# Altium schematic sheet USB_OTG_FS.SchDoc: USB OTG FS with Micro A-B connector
size A4; Date: 25-FEB-2015; Author: A.B; CompanyName: STMicroelectronics; Address1: 12, Rue Jules HOROWITZ; Address2: 38019 Grenoble; Address3: FRANCE; DocumentNumber: MB1191; Revision: B-02; SheetNumber: 8; SheetTotal: 13; Project: STM32F746G-DISCO
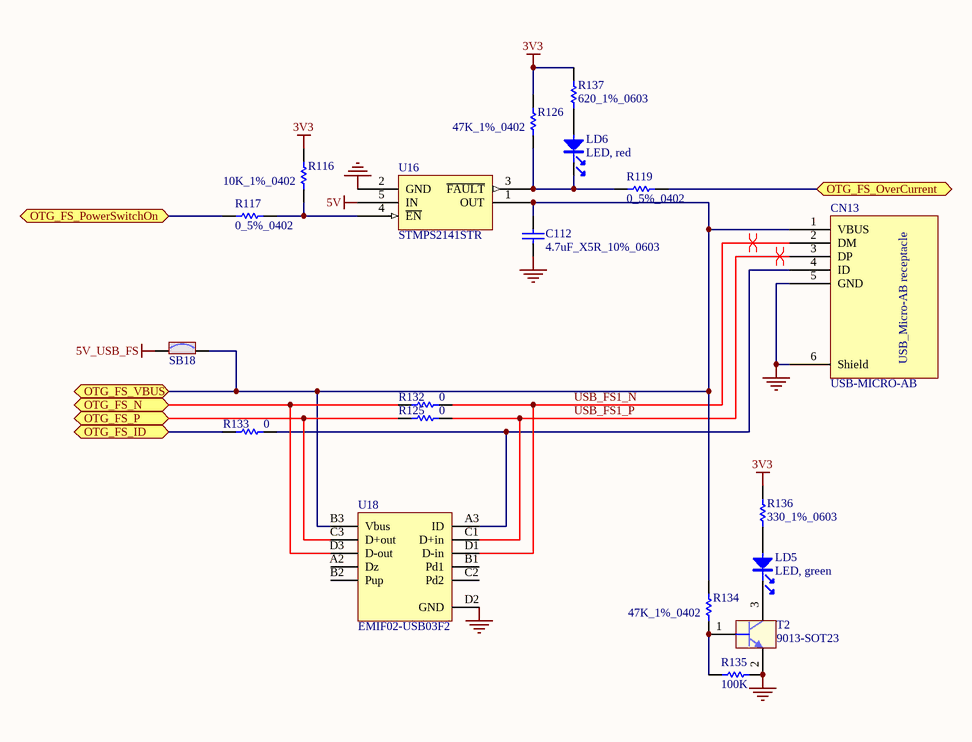
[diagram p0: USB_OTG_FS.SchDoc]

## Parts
C112  4.7uF_X5R_10%_0603  [0603C]
CN13  USB-MICRO-AB  [USB-MICRO-AB]
LD5  LED, green  [0603D]
LD6  LED, red  [0603D]
R116  10K_1%_0402  [0402R]
R117  0_5%_0402  [0402R]
R119  0_5%_0402  [0402R]
R125  0  [0402R]
R126  47K_1%_0402  [0402R]
R132  0  [0402R]
R133  0  [0402R]
R134  47K_1%_0402  [0402R]
R135  100K  [0402R]
R136  330_1%_0603  [0603R]
R137  620_1%_0603  [0603R]
SB18  Solder Bridge ON  [JP2_SMD]  (value not drawn)
T2  9013-SOT23  [SOT23]
U16  STMPS2141STR  [SOT23-5L]
U18  EMIF02-USB03F2  [Flip Chip]

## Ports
OTG_FS_ID, OTG_FS_N, OTG_FS_OverCurrent, OTG_FS_P, OTG_FS_PowerSwitchOn, OTG_FS_VBUS

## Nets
3V3: R116.2 R126.2 R136.2 R137.2
5V: U16.5(IN)
5V_USB_FS: SB18.1
GND: C112.1 CN13.5(GND) CN13.6(Shield) R135.2 T2.2(E) U16.2(GND) U18.D2(GND)
OTG_FS_ID: R133.1 ; port OTG_FS_ID
OTG_FS_N: R132.1 U18.D3(D-out) ; port OTG_FS_N
OTG_FS_OverCurrent: R119.2 ; port OTG_FS_OverCurrent
OTG_FS_P: R125.1 U18.C3(D+out) ; port OTG_FS_P
OTG_FS_PowerSwitchOn: R117.1 ; port OTG_FS_PowerSwitchOn
OTG_FS_VBUS: C112.2 CN13.1(VBUS) R134.2 SB18.2 U16.1(OUT) U18.B3(Vbus) ; port OTG_FS_VBUS
USB_FS1_N: CN13.2(DM) R132.2 U18.D1(D-in)
USB_FS1_P: CN13.3(DP) R125.2 U18.C1(D+in)
NetCN13_4: CN13.4(ID) R133.2 U18.A3(ID)
NetLD5_1: LD5.1 R136.1
NetLD5_2: LD5.2 T2.3(C)
NetLD6_1: LD6.1 R137.1
NetLD6_2: LD6.2 R119.1 R126.1 U16.3(~{FAULT})
NetR116_1: R116.1 R117.2 U16.4(~{EN})
NetR134_1: R134.1 R135.1 T2.1(B)

Not connected (* = marked no-connect by the designer): U18 A2(Dz) B1(Pd1) B2(Pup) C2(Pd2)

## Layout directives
differential pair: USB_FS1_N, USB_FS1_P

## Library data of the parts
C112 = Cap_4.7uF_X5R_10%_0603: Capacitor,4.7uF,16V, X5R,10%,0603,YAGEO; Manuf_Part_1: CC0603KRX5R7BB475; Order: CC0603KRX5R7BB105
CN13 = USB-MICRO-AB: USB-MICRO-AB, 47590-0001, SMT, MOLEX; Ref St: xxxxxxx
LD5 = LED_green: LED, green, 0603; Manuf_1: everlight; Manuf_Part_1: 19-213SYGC/S530-E2/TR8; Description: LED,green,0603,19-213SYGC/S530-E2/TR8,everlight; ECCN_US/EU: EAR99/NEC
LD6 = LED_red: LED, red, 0603; Manuf_1: everlight; Manuf_Part_1: 19-213-R6C-AP1Q2B/3T; Description: LED,red,0603,19-213-R6C-AP1Q2B/3T,everlight; ECCN_US/EU: EAR99/NEC
R116 = Res_10K_1%_0402: Resistor,10K,0402,1%,YAGEO; Manuf_Part_1: RC0402FR-0710KL
R117 R119 = Res_0_5%_0402: Resistor,0,0402,5%,YAGEO; Manuf_Part_1: RC0402JR-070RL; Value: 0; Order: 2363467
R125 R132 R133 = Res_0_5%_0402: Resistor,0,0402,5%,YAGEO; Manuf_Part_1: RC0402JR-070RL; Order: 2363467
R126 R134 = Res_47K_1%_0402: Resistor,47K,0402,1%,YAGEO; Manuf_Part_1: RC0402FR-0747KL; Order: 9239430
R135 = Res_100K_1%_0402: Resistor,100K,0402,1%,YAGEO; Manuf_Part_1: RT0402FRE07100KL
R136 = Res_330_1%_0603: Resistor,330,0603,1%,YAGEO; Manuf_Part_1: RT0603FRE07330RL; Value: 330; Order: 1500622RL
R137 = Res_620_1%_0603: Resistor,620,0603,1%,VISHAY; Manuf_Part_1: CRCW0603620RFKEA; Manuf_1: VISHAY DRALORIC; Value: 620; Order: 2122341
SB18 = SB_ON: Solder: YES
T2 = 9013-SOT23: NPN Bipolar Transistor; Manuf_1: NXP; Manuf_Part_1: BSR14; Description: NPN Bipolar Transistor, SOT-23 Footprint; Order: 1081310; ECCN_US/EU: EAR99/NEC
U16 = STMPS2141STR: Enhanced single channel power switches; Manuf_1: STM; Provided: ST; ECCN_US/EU: EAR99/NEC; Ref St: 9159003
U18 = EMIF02-USB03F2: 2-line IPAD, EMI filter including ESD protection; Manuf_1: STM; Provided: ST; ECCN_US/EU: EAR99/NEC; Ref St: 9179037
